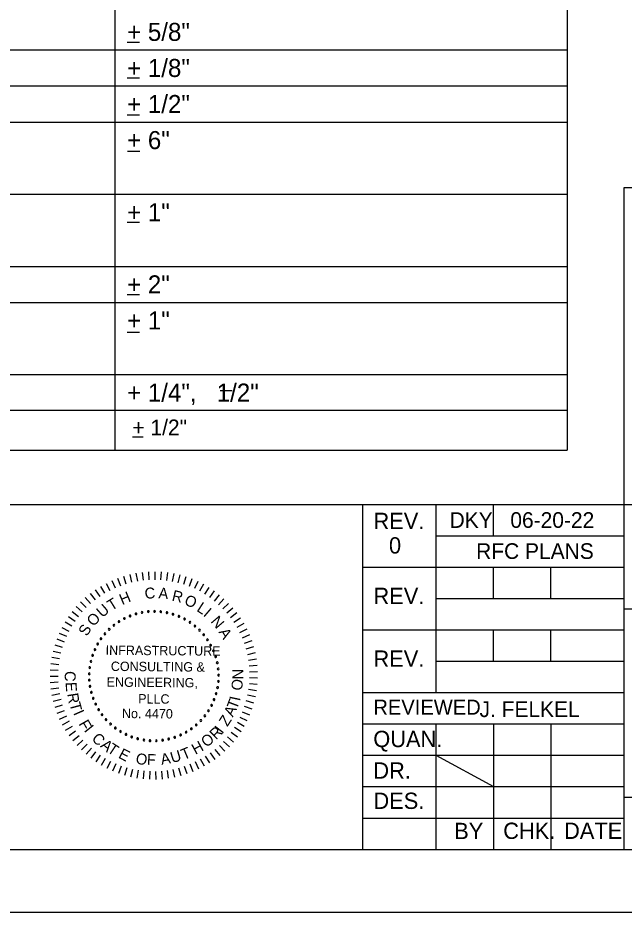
# Model space of a CAD drawing. Extents: x -55.6 to -19.5, y -5.1 to 16.9.
# Drawn here: x -30.34 to -25.5, y -5.09 to 2.04 of the extents above; entities that cross this region are included whole.
import ezdxf

# ---------------------------------------------------------------- set-up
doc = ezdxf.new("R2010")
doc.units = 0
for name, color, linetype in [('BR_BORDER LINES', 7, 'Continuous'), ('BR_TABLE LINES', 7, 'Continuous'), ('BR_TEXT', 7, 'Continuous'), ('Level 31', 7, 'Continuous')]:
    doc.layers.add(name, color=color, linetype=linetype)

msp = doc.modelspace()

# ---------------------------------------------------------------- linework, layer by layer
at = {"layer": 'BR_BORDER LINES'}
for p, q in [((-25.9542, 8.7992), (-25.9542, -1.4104)), ((-25.5009, -4.5917), (-25.5009, 0.6849)), ((-25.5009, 0.6849), (-20.084, 0.6849)), ((-35.3047, -1.4104), (-25.9542, -1.4104)), ((-32.9495, -1.8415), (-27.5843, -1.8415)), ((-27.5843, -4.5917), (-27.5843, -1.8415)), ((-27.5843, -1.8415), (-20.084, -1.8415)), ((-27.001, -1.8415), (-27.001, -3.3416)), ((-26.5426, -2.0916), (-26.5426, -1.8415)), ((-27.001, -2.0916), (-25.5009, -2.0916)), ((-27.5843, -2.3416), (-25.5009, -2.3416)), ((-26.5426, -2.5916), (-26.5426, -2.3416)), ((-26.0843, -2.5916), (-26.0843, -2.3416)), ((-27.001, -2.5916), (-25.5009, -2.5916)), ((-25.5009, -2.6749), (-25.5009, -2.6749)), ((-25.5009, -2.6749), (-20.0838, -2.6749)), ((-27.5843, -2.8416), (-25.5009, -2.8416)), ((-26.5426, -3.0916), (-26.5426, -2.8416)), ((-26.0843, -3.0916), (-26.0843, -2.8416)), ((-27.001, -3.0916), (-25.5009, -3.0916)), ((-27.5843, -3.3416), (-25.5009, -3.3416)), ((-27.5843, -3.5916), (-25.5009, -3.5916)), ((-27.001, -3.5916), (-27.001, -4.5917)), ((-26.5426, -3.5916), (-26.5426, -4.5917)), ((-26.0843, -3.5916), (-26.0843, -4.5917)), ((-27.5843, -3.8416), (-25.5009, -3.8416)), ((-27.5843, -4.0916), (-25.5009, -4.0916)), ((-25.5009, -4.175), (-20.084, -4.175)), ((-27.5843, -4.3416), (-25.5009, -4.3416)), ((-53.7501, -4.5917), (-20.084, -4.5917))]:
    msp.add_line(p, q, dxfattribs=at)
at = {"layer": 'BR_TABLE LINES'}
for p, q in [((-29.5618, 8.7992), (-29.5618, -1.4104)), ((-35.3047, 1.7804), (-25.9542, 1.7804)), ((-35.3047, 1.4929), (-25.9542, 1.4929)), ((-35.3047, 1.2054), (-25.9542, 1.2054)), ((-35.3047, 0.6304), (-25.9542, 0.6304)), ((-35.3047, 0.0554), (-25.9542, 0.0554)), ((-35.3047, -0.2321), (-25.9542, -0.2321)), ((-35.3047, -0.8071), (-25.9542, -0.8071)), ((-35.3047, -1.0912), (-25.9542, -1.0912))]:
    msp.add_line(p, q, dxfattribs=at)
at = {"layer": 'BR_TEXT'}
for p, q in [((-29.4639, 1.8425), (-29.3665, 1.8425)), ((-29.4639, 1.5568), (-29.3665, 1.5568)), ((-29.4639, 1.2637), (-29.3665, 1.2637)), ((-29.4602, 0.9743), (-29.3628, 0.9743)), ((-29.4639, 0.4065), (-29.3665, 0.4065)), ((-29.4639, -0.1686), (-29.3665, -0.1686)), ((-29.4639, -0.4692), (-29.3665, -0.4692)), ((-28.7225, -0.9349), (-28.6251, -0.9349)), ((-29.4216, -1.3025), (-29.3369, -1.3025)), ((-29.4918, -2.4141), (-29.4732, -2.475)), ((-29.4431, -2.4008), (-29.4282, -2.4627)), ((-29.3936, -2.3906), (-29.3826, -2.4533)), ((-29.3437, -2.3834), (-29.3365, -2.4467)), ((-29.2934, -2.3793), (-29.29, -2.4429)), ((-29.2429, -2.3782), (-29.2434, -2.4419)), ((-29.1924, -2.3802), (-29.1969, -2.4438)), ((-29.1422, -2.3853), (-29.1505, -2.4485)), ((-29.0924, -2.3935), (-29.1045, -2.456)), ((-29.0432, -2.4046), (-29.0591, -2.4663)), ((-28.9947, -2.4188), (-29.0143, -2.4793)), ((-29.6319, -2.4712), (-29.6025, -2.5276)), ((-29.5864, -2.4493), (-29.5605, -2.5075)), ((-29.5396, -2.4302), (-29.5173, -2.4899)), ((-28.9472, -2.4358), (-28.9705, -2.4951)), ((-28.9008, -2.4558), (-28.9277, -2.5135)), ((-28.8557, -2.4785), (-28.8861, -2.5345)), ((-29.7592, -2.5528), (-29.72, -2.603)), ((-29.7185, -2.523), (-29.6824, -2.5755)), ((-29.676, -2.4958), (-29.6432, -2.5503)), ((-28.8121, -2.5039), (-28.8458, -2.558)), ((-28.7701, -2.532), (-28.8071, -2.5839)), ((-28.73, -2.5625), (-28.77, -2.6121)), ((-29.8349, -2.6195), (-29.7899, -2.6646)), ((-29.7981, -2.585), (-29.7559, -2.6327)), ((-28.6917, -2.5955), (-28.7347, -2.6425)), ((-28.6555, -2.6307), (-28.7013, -2.675)), ((-29.9019, -2.695), (-29.8518, -2.7342)), ((-29.8696, -2.6562), (-29.8219, -2.6985)), ((-28.6216, -2.6681), (-28.6699, -2.7095)), ((-28.59, -2.7074), (-28.6407, -2.7458)), ((-29.9593, -2.778), (-29.9047, -2.8109)), ((-29.9319, -2.7356), (-29.8794, -2.7717)), ((-28.5608, -2.7486), (-28.6138, -2.7839)), ((-29.984, -2.822), (-29.9276, -2.8515)), ((-28.5342, -2.7915), (-28.5893, -2.8235)), ((-28.5103, -2.836), (-28.5672, -2.8645)), ((-30.0253, -2.9141), (-29.9657, -2.9365)), ((-30.0061, -2.8674), (-29.948, -2.8934)), ((-28.4891, -2.8818), (-28.5477, -2.9068)), ((-30.0417, -2.9619), (-29.9808, -2.9806)), ((-28.4708, -2.9289), (-28.5307, -2.9502)), ((-28.4553, -2.9769), (-28.5165, -2.9946)), ((-30.0655, -3.06), (-30.0028, -3.0711)), ((-30.0551, -3.0106), (-29.9932, -3.0255)), ((-28.4428, -3.0258), (-28.505, -3.0398)), ((-30.0729, -3.1099), (-30.0096, -3.1172)), ((-28.4334, -3.0754), (-28.4962, -3.0855)), ((-28.4269, -3.1255), (-28.4903, -3.1318)), ((-30.0772, -3.1602), (-30.0136, -3.1636)), ((-28.4236, -3.1759), (-28.4872, -3.1783)), ((-30.0784, -3.2107), (-30.0148, -3.2102)), ((-30.0766, -3.2611), (-30.0131, -3.2568)), ((-28.4261, -3.2768), (-28.4895, -3.2714)), ((-28.4233, -3.2264), (-28.4869, -3.2249)), ((-30.0717, -3.3114), (-30.0086, -3.3032)), ((-30.0637, -3.3612), (-30.0012, -3.3492)), ((-28.4319, -3.3269), (-28.4949, -3.3177)), ((-30.0528, -3.4105), (-29.9911, -3.3947)), ((-28.4527, -3.4257), (-28.5141, -3.4088)), ((-28.4408, -3.3766), (-28.5031, -3.3635)), ((-30.0388, -3.459), (-29.9782, -3.4395)), ((-30.0219, -3.5066), (-29.9626, -3.4834)), ((-28.4676, -3.4739), (-28.5279, -3.4534)), ((-30.0021, -3.553), (-29.9444, -3.5263)), ((-28.5061, -3.5672), (-28.5634, -3.5395)), ((-28.4854, -3.5211), (-28.5443, -3.497)), ((-29.9796, -3.5982), (-29.9235, -3.5679)), ((-29.9543, -3.6419), (-29.9002, -3.6083)), ((-28.5556, -3.6552), (-28.6091, -3.6207)), ((-28.5295, -3.6119), (-28.585, -3.5808)), ((-29.9264, -3.684), (-29.8745, -3.6471)), ((-29.896, -3.7243), (-29.8464, -3.6843)), ((-28.6154, -3.7364), (-28.6643, -3.6957)), ((-28.5842, -3.6967), (-28.6356, -3.659)), ((-29.8632, -3.7627), (-29.8161, -3.7198)), ((-29.8281, -3.799), (-29.7838, -3.7533)), ((-28.6847, -3.8098), (-28.7283, -3.7634)), ((-28.6489, -3.7742), (-28.6953, -3.7305)), ((-29.7909, -3.833), (-29.7494, -3.7848)), ((-29.7517, -3.8648), (-29.7132, -3.8141)), ((-29.7105, -3.8941), (-29.6752, -3.8411)), ((-28.7624, -3.8742), (-28.8, -3.8228)), ((-28.7226, -3.8432), (-28.7633, -3.7942)), ((-29.6677, -3.9209), (-29.6357, -3.8658)), ((-29.6234, -3.945), (-29.5948, -3.8881)), ((-29.5776, -3.9663), (-29.5525, -3.9078)), ((-28.9383, -3.9724), (-28.9624, -3.9134)), ((-28.8922, -3.9519), (-28.9198, -3.8945)), ((-28.8474, -3.9287), (-28.8785, -3.8731)), ((-28.8041, -3.9027), (-28.8385, -3.8492)), ((-29.5307, -3.9848), (-29.5092, -3.9249)), ((-29.4826, -4.0004), (-29.4649, -3.9393)), ((-29.4338, -4.0131), (-29.4198, -3.951)), ((-29.3842, -4.0228), (-29.374, -3.9599)), ((-29.3342, -4.0294), (-29.3278, -3.966)), ((-29.2838, -4.0329), (-29.2814, -3.9693)), ((-29.2333, -4.0334), (-29.2348, -3.9698)), ((-29.1829, -4.0308), (-29.1882, -3.9674)), ((-29.1328, -4.0251), (-29.1419, -3.9621)), ((-29.083, -4.0164), (-29.096, -3.9541)), ((-29.0339, -4.0047), (-29.0507, -3.9433)), ((-28.9856, -3.99), (-29.0061, -3.9297))]:
    msp.add_line(p, q, dxfattribs=at)
for centre, start, end in [((-29.393, -2.7144), 16.14222, 196.14222), ((-29.3445, -2.703), 10.60376, 190.60376), ((-29.3445, -2.703), 190.60376, 10.60376), ((-29.2951, -2.6963), 5.06529, 185.06529), ((-29.2951, -2.6963), 185.06529, 5.06529), ((-29.2453, -2.6944), 359.52683, 179.52683), ((-29.2453, -2.6944), 179.52683, 359.52683), ((-29.1956, -2.6973), 173.98837, 353.98837), ((-29.1956, -2.6973), 353.98837, 173.98837), ((-29.1463, -2.705), 168.44991, 348.44991), ((-29.1463, -2.705), 348.44991, 168.44991), ((-29.5288, -2.7758), 32.7576, 212.7576), ((-29.5288, -2.7758), 212.7576, 32.7576), ((-29.4856, -2.751), 27.21914, 207.21914), ((-29.4856, -2.751), 207.21914, 27.21914), ((-29.4402, -2.7304), 21.68068, 201.68068), ((-29.4402, -2.7304), 201.68068, 21.68068), ((-29.393, -2.7144), 196.14222, 16.14222), ((-29.0981, -2.7174), 162.91145, 342.91145), ((-29.0981, -2.7174), 342.91145, 162.91145), ((-29.0513, -2.7344), 157.37299, 337.37299), ((-29.0513, -2.7344), 337.37299, 157.37299), ((-29.0063, -2.7559), 151.83453, 331.83453), ((-29.0063, -2.7559), 331.83453, 151.83453), ((-28.9636, -2.7816), 146.29606, 326.29606), ((-28.9636, -2.7816), 326.29606, 146.29606), ((-29.607, -2.8373), 43.83453, 223.83453), ((-29.607, -2.8373), 223.83453, 43.83453), ((-29.5694, -2.8047), 38.29606, 218.29606), ((-29.5694, -2.8047), 218.29606, 38.29606), ((-28.9236, -2.8113), 140.7576, 320.7576), ((-28.9236, -2.8113), 320.7576, 140.7576), ((-28.8866, -2.8447), 135.21914, 315.21914), ((-28.8866, -2.8447), 315.21914, 135.21914), ((-29.672, -2.9128), 54.91145, 234.91145), ((-29.672, -2.9128), 234.91145, 54.91145), ((-29.6413, -2.8735), 49.37299, 229.37299), ((-29.6413, -2.8735), 229.37299, 49.37299), ((-28.8531, -2.8816), 129.68068, 309.68068), ((-28.8531, -2.8816), 309.68068, 129.68068), ((-28.8232, -2.9215), 124.14222, 304.14222), ((-28.8232, -2.9215), 304.14222, 124.14222), ((-29.7213, -2.9993), 65.98837, 245.98837), ((-29.7213, -2.9993), 245.98837, 65.98837), ((-29.6987, -2.9548), 60.44991, 240.44991), ((-29.6987, -2.9548), 240.44991, 60.44991), ((-28.7974, -2.9641), 118.60376, 298.60376), ((-28.7974, -2.9641), 298.60376, 118.60376), ((-29.7394, -3.0457), 71.52683, 251.52683), ((-29.7394, -3.0457), 251.52683, 71.52683), ((-28.7757, -3.0089), 113.06529, 293.06529), ((-28.7757, -3.0089), 293.06529, 113.06529), ((-28.7585, -3.0557), 107.52683, 287.52683), ((-28.7585, -3.0557), 287.52683, 107.52683), ((-29.7619, -3.1426), 82.60376, 262.60376), ((-29.7619, -3.1426), 262.60376, 82.60376), ((-29.753, -3.0936), 77.06529, 257.06529), ((-29.753, -3.0936), 257.06529, 77.06529), ((-28.7459, -3.1039), 101.98837, 281.98837), ((-28.7459, -3.1039), 281.98837, 101.98837), ((-29.766, -3.1923), 88.14222, 268.14222), ((-29.766, -3.1923), 268.14222, 88.14222), ((-28.7381, -3.1531), 96.44991, 276.44991), ((-28.735, -3.2029), 90.91145, 270.91145), ((-28.7381, -3.1531), 276.44991, 96.44991), ((-28.735, -3.2029), 270.91145, 90.91145), ((-29.7653, -3.2421), 93.68068, 273.68068), ((-29.7653, -3.2421), 273.68068, 93.68068), ((-28.7367, -3.2527), 85.37299, 265.37299), ((-28.7367, -3.2527), 265.37299, 85.37299), ((-29.7598, -3.2917), 99.21914, 279.21914), ((-29.7598, -3.2917), 279.21914, 99.21914), ((-29.7496, -3.3404), 104.7576, 284.7576), ((-29.7496, -3.3404), 284.7576, 104.7576), ((-28.7544, -3.3506), 74.29606, 254.29606), ((-28.7544, -3.3506), 254.29606, 74.29606), ((-28.7432, -3.3021), 79.83453, 259.83453), ((-28.7432, -3.3021), 259.83453, 79.83453), ((-29.7346, -3.388), 110.29606, 290.29606), ((-29.7346, -3.388), 290.29606, 110.29606), ((-28.7703, -3.3978), 68.7576, 248.7576), ((-28.7703, -3.3978), 248.7576, 68.7576), ((-29.7152, -3.4339), 115.83453, 295.83453), ((-29.7152, -3.4339), 295.83453, 115.83453), ((-29.6914, -3.4777), 121.37299, 301.37299), ((-29.6914, -3.4777), 301.37299, 121.37299), ((-28.8153, -3.4866), 57.68068, 237.68068), ((-28.8153, -3.4866), 237.68068, 57.68068), ((-28.7907, -3.4433), 63.21914, 243.21914), ((-28.7907, -3.4433), 243.21914, 63.21914), ((-29.6636, -3.5189), 126.91145, 306.91145), ((-29.6636, -3.5189), 306.91145, 126.91145), ((-29.6318, -3.5574), 132.44991, 312.44991), ((-29.6318, -3.5574), 312.44991, 132.44991), ((-28.8766, -3.5651), 46.60376, 226.60376), ((-28.8766, -3.5651), 226.60376, 46.60376), ((-28.8441, -3.5273), 52.14222, 232.14222), ((-28.8441, -3.5273), 232.14222, 52.14222), ((-29.5965, -3.5925), 137.98837, 317.98837), ((-29.5965, -3.5925), 317.98837, 137.98837), ((-29.558, -3.6241), 143.52683, 323.52683), ((-29.558, -3.6241), 323.52683, 143.52683), ((-28.9518, -3.6303), 35.52683, 215.52683), ((-28.9518, -3.6303), 215.52683, 35.52683), ((-28.9126, -3.5995), 41.06529, 221.06529), ((-28.9126, -3.5995), 221.06529, 41.06529), ((-29.5166, -3.6519), 149.06529, 329.06529), ((-29.5166, -3.6519), 329.06529, 149.06529), ((-29.4727, -3.6755), 154.60376, 334.60376), ((-29.4727, -3.6755), 334.60376, 154.60376), ((-29.4267, -3.6947), 160.14222, 340.14222), ((-29.4267, -3.6947), 340.14222, 160.14222), ((-29.3791, -3.7095), 345.68068, 165.68068), ((-29.1323, -3.712), 13.37299, 193.37299), ((-29.0844, -3.6982), 18.91145, 198.91145), ((-29.0844, -3.6982), 198.91145, 18.91145), ((-29.0381, -3.6799), 24.44991, 204.44991), ((-29.0381, -3.6799), 204.44991, 24.44991), ((-28.9937, -3.6572), 29.98837, 209.98837), ((-28.9937, -3.6572), 209.98837, 29.98837), ((-29.3791, -3.7095), 165.68068, 345.68068), ((-29.3303, -3.7195), 351.21914, 171.21914), ((-29.3303, -3.7195), 171.21914, 351.21914), ((-29.2808, -3.7249), 356.7576, 176.7576), ((-29.2808, -3.7249), 176.7576, 356.7576), ((-29.231, -3.7254), 2.29606, 182.29606), ((-29.231, -3.7254), 182.29606, 2.29606), ((-29.1813, -3.7211), 7.83453, 187.83453), ((-29.1813, -3.7211), 187.83453, 7.83453), ((-29.1323, -3.712), 193.37299, 13.37299)]:
    msp.add_arc(centre, 0.00701, start, end, dxfattribs=at)
at = {"layer": 'Level 31'}
msp.add_line((-27.001, -3.8416), (-26.5426, -4.0916), dxfattribs=at)
msp.add_lwpolyline([(-55.5834, -5.0916), (-19.5834, -5.0916), (-19.5834, 16.9084), (-55.5834, 16.9084)], close=True, dxfattribs=at)

# ---------------------------------------------------------------- texts
at = {"layer": 'BR_TEXT'}
for s, height, p in [('+ 5/8"', 0.14375, (-29.4644, 1.8523)), ('+ 1/8"', 0.14375, (-29.4644, 1.5648)), ('+ 1/2"', 0.14375, (-29.4644, 1.2773)), ('+ 6"', 0.14375, (-29.4644, 0.9898)), ('+ 1"', 0.14375, (-29.4644, 0.4148)), ('+ 2"', 0.14375, (-29.4644, -0.1602)), ('+ 1"', 0.14375, (-29.4644, -0.4477)), ('+ 1/4",   1/2"', 0.14375, (-29.4644, -1.0227)), ('+ 1/2"', 0.125, (-29.422, -1.2907)), ('REV.', 0.13001, (-27.4996, -2.0386)), ('DKY', 0.12499, (-26.8926, -2.0291)), ('06-20-22', 0.12499, (-26.4082, -2.0291)), ('0', 0.13, (-27.3758, -2.2336)), ('RFC PLANS', 0.12499, (-26.681, -2.2766)), ('REV.', 0.13001, (-27.4996, -2.6362)), ('REV.', 0.13001, (-27.4996, -3.1362)), ('REVIEWED', 0.12, (-27.5003, -3.5181)), ('J. FELKEL', 0.125, (-26.6538, -3.5372)), ('QUAN.', 0.13001, (-27.5009, -3.7765)), ('DR.', 0.13001, (-27.5007, -4.028)), ('DES.', 0.13001, (-27.4997, -4.2693)), ('BY', 0.13001, (-26.8556, -4.5097)), ('CHK.', 0.13001, (-26.4648, -4.5083)), ('DATE', 0.13001, (-25.9796, -4.5082))]:
    msp.add_text(s, height=height, dxfattribs=at).set_placement(p)
for s, height, rotation, p in [('H', 0.0872, 22.78817, (-29.5037, -2.6452)), ('C', 0.0872, 4.72812, (-29.3208, -2.5958)), ('A', 0.0872, 355.69809, (-29.2164, -2.5909)), ('R', 0.0872, 346.66807, (-29.1121, -2.6078)), ('U', 0.0872, 40.84822, (-29.6618, -2.749)), ('T', 0.0872, 31.81819, (-29.5885, -2.6929)), ('O', 0.0872, 337.63804, (-29.0143, -2.6377)), ('L', 0.0872, 327.10802, (-28.9155, -2.6881)), ('I', 0.0872, 319.578, (-28.8629, -2.7259)), ('O', 0.0872, 49.87824, (-29.7288, -2.82)), ('N', 0.0872, 310.54797, (-28.8021, -2.7767)), ('S', 0.0872, 58.90827, (-29.7842, -2.8982)), ('A', 0.0872, 301.51795, (-28.7371, -2.8591)), ('INFRASTRUCTURE', 0.074771, 359.52683, (-29.6356, -3.0407)), ('CONSULTING &', 0.074771, 359.52683, (-29.5943, -3.1693)), ('C', 0.0872, 267.02504, (-29.9592, -3.1681)), ('N', 0.0872, 89.20849, (-28.5378, -3.2379)), ('E', 0.0872, 273.02504, (-29.9548, -3.2597)), ('ENGINEERING,', 0.074771, 359.52683, (-29.6279, -3.2947)), ('O', 0.0872, 83.20849, (-28.5488, -3.3293)), ('R', 0.0872, 279.02504, (-29.942, -3.352)), ('T', 0.0872, 285.02504, (-29.9246, -3.4307)), ('PLLC', 0.07477, 359.52683, (-29.3762, -3.4283)), ('T', 0.0872, 69.39539, (-28.5901, -3.4811)), ('I', 0.0872, 77.90926, (-28.5644, -3.4136)), ('I', 0.0872, 293.77127, (-29.8949, -3.5038)), ('No. 4470', 0.07477, 359.52683, (-29.5057, -3.5452)), ('A', 0.0872, 63.39539, (-28.6209, -3.5414)), ('F', 0.0872, 299.77127, (-29.8538, -3.5899)), ('Z', 0.0872, 57.39539, (-28.6647, -3.6178)), ('I', 0.0872, 308.52683, (-29.8117, -3.6438)), ('R', 0.0872, 44.52683, (-28.7551, -3.7227)), ('I', 0.0872, 52.33388, (-28.7058, -3.6755)), ('C', 0.0872, 314.52683, (-29.7523, -3.7139)), ('O', 0.0872, 38.52683, (-28.8317, -3.7827)), ('A', 0.0872, 320.52683, (-29.6832, -3.7725)), ('T', 0.0872, 326.52683, (-29.6287, -3.8109)), ('T', 0.0872, 22.52683, (-29.013, -3.8805)), ('H', 0.0872, 28.52683, (-28.9198, -3.8387)), ('E', 0.0872, 332.52683, (-29.5401, -3.8587)), ('O', 0.0872, 350.52683, (-29.4, -3.9076)), ('F', 0.0872, 356.52683, (-29.3085, -3.9167)), ('A', 0.0872, 10.52683, (-29.1887, -3.9184)), ('U', 0.0872, 16.52683, (-29.1047, -3.9049))]:
    msp.add_text(s, height=height, rotation=rotation, dxfattribs=at).set_placement(p)

doc.saveas('drawing.dxf')
